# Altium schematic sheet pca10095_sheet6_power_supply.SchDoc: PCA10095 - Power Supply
size A3; Organization: Nordic Semiconductor; DocumentNumber: 6; SheetNumber: 6; SheetTotal: 6; CompanyName: Nordic Semiconductor
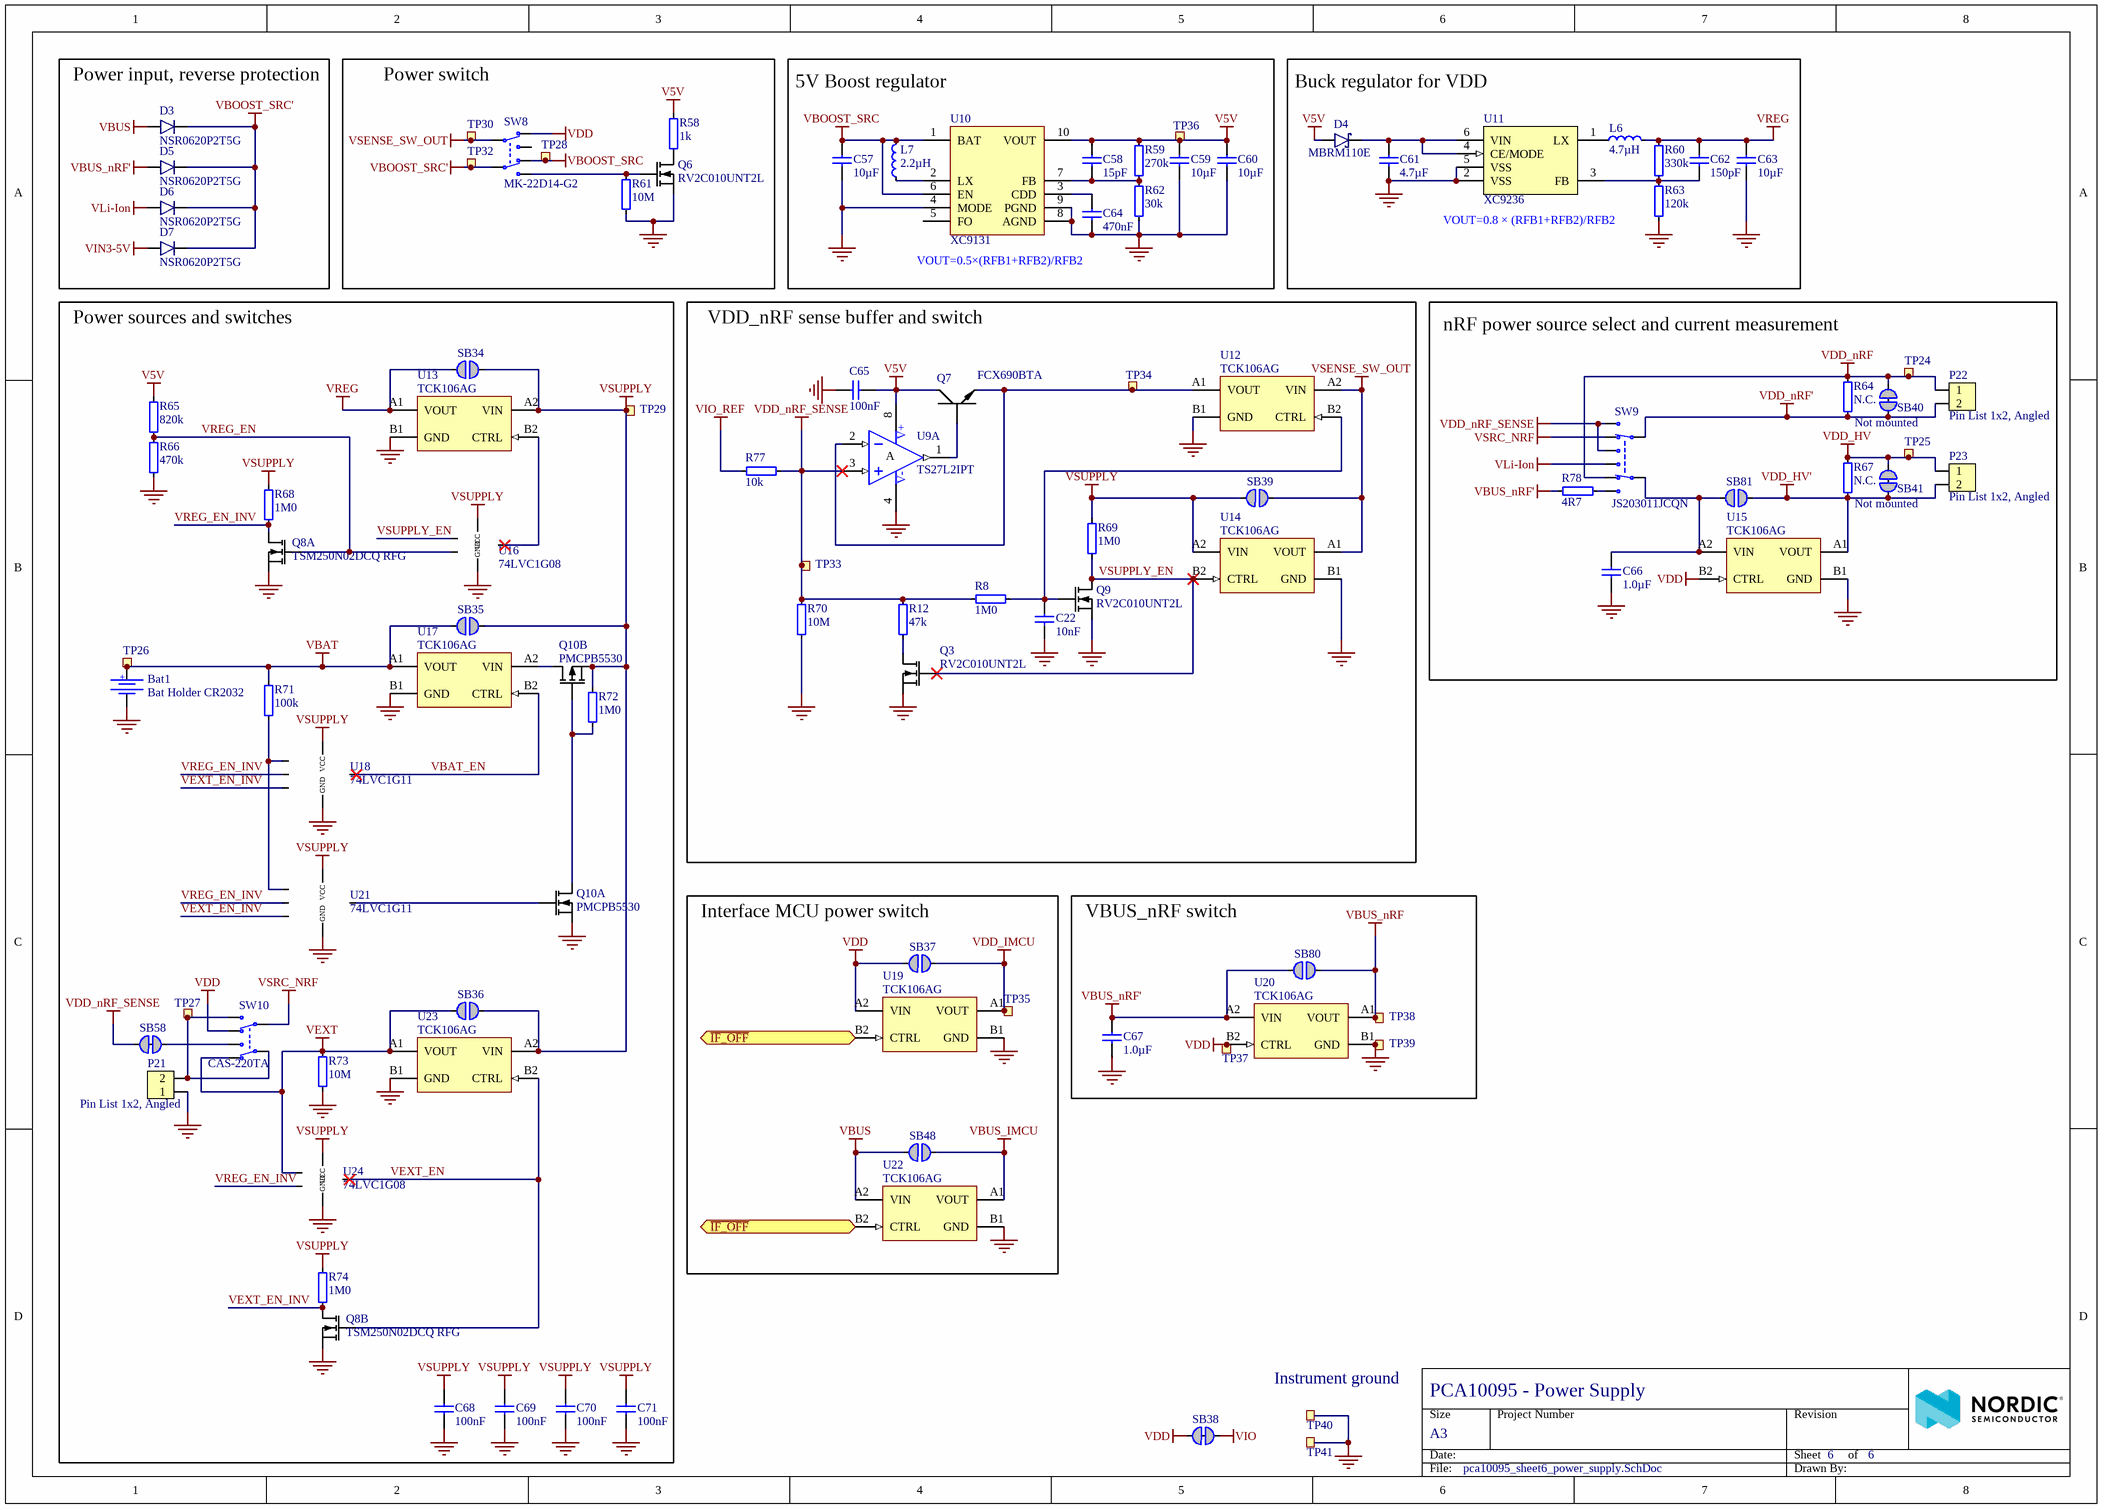
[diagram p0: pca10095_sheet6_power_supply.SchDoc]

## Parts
Bat1  Bat Holder CR2032  [L-KLS5-CR2032-23-B1]
C22  10nF  [CAPC0603X03L_C]
C57  10µF  [CAPC1608X06L]
C58  15pF  [CAPC0603X03L_C]
C59  10µF  [CAPC1608X06L]
C60  10µF  [CAPC1608X06L]
C61  4.7µF  [CAPC1005X04L]
C62  150pF  [CAPC0603X03L_C]
C63  10µF  [CAPC1608X06L]
C64  470nF  [CAPC0603X03L_C]
C65  100nF  [CAPC0603X03L_C]
C66  1.0µF  [CAPC1005X04L]
C67  1.0µF  [CAPC1608X06L]
C68  100nF  [CAPC0603X03L_C]
C69  100nF  [CAPC0603X03L_C]
C70  100nF  [CAPC0603X03L_C]
C71  100nF  [CAPC0603X03L_C]
D3  NSR0620P2T5G  [SODFL100X40-2N]
D4  MBRM110E  [DO-216AA]
D5  NSR0620P2T5G  [SODFL100X40-2N]
D6  NSR0620P2T5G  [SODFL100X40-2N]
D7  NSR0620P2T5G  [SODFL100X40-2N]
L6  4.7µH  [TY-NR3015]
L7  2.2µH  [TY-NR3015]
P21  Pin List 1x2, Angled  [LIST_ANG_1x2-SMD-2.54MM]
P22  Pin List 1x2, Angled  [LIST_ANG_1x2-SMD-2.54MM]
P23  Pin List 1x2, Angled  [LIST_ANG_1x2-SMD-2.54MM]
Q3  RV2C010UNT2L  [DFN65P100X40-3L]
Q6  RV2C010UNT2L  [DFN65P100X40-3L]
Q7  FCX690BTA  [SOT89-150P409X160-3N]
Q8  TSM250N02DCQ RFG  [DFN65P200X200X80_HS-6N]  (parts A,B of 2)
Q9  RV2C010UNT2L  [DFN65P100X40-3L]
Q10  PMCPB5530  [PMCPB5530X]  (parts A,B of 2)
R8  1M0  [RESC0603X03L_C]
R12  47k  [RESC0603X03L_C]
R58  1k  [RESC0603X03L_C]
R59  270k  [RESC0603X03L_C]
R60  330k  [RESC0603X03L_C]
R61  10M  [RESC0603X03L_C]
R62  30k  [RESC0603X03L_C]
R63  120k  [RESC0603X03L_C]
R64  N.C.  Assembly: Not mounted  [RESC1005X04L_NC]
R65  820k  [RESC0603X03L_C]
R66  470k  [RESC0603X03L_C]
R67  N.C.  Assembly: Not mounted  [RESC1005X04L_NC]
R68  1M0  [RESC0603X03L_C]
R69  1M0  [RESC0603X03L_C]
R70  10M  [RESC0603X03L_C]
R71  100k  [RESC0603X03L_C]
R72  1M0  [RESC0603X03L_C]
R73  10M  [RESC0603X03L_C]
R74  1M0  [RESC0603X03L_C]
R77  10k  [RESC0603X03L_C]
R78  4R7  [RESC0603X03L_C]
SB34  Solderbridge  [Solderbridge]  (value not drawn)  (no BOM)
SB35  Solderbridge  [Solderbridge]  (value not drawn)  (no BOM)
SB36  Solderbridge  [Solderbridge]  (value not drawn)  (no BOM)
SB37  Solderbridge  [Solderbridge]  (value not drawn)  (no BOM)
SB38  Solderbridge  [Solderbridge_Shorted]  (value not drawn)  (net tie, no BOM)
SB39  Solderbridge  [Solderbridge]  (value not drawn)  (no BOM)
SB40  Solderbridge  [Solderbridge_Shorted]  (value not drawn)  (net tie, no BOM)
SB41  Solderbridge  [Solderbridge_Shorted]  (value not drawn)  (net tie, no BOM)
SB48  Solderbridge  [Solderbridge]  (value not drawn)  (no BOM)
SB58  Solderbridge  [Solderbridge_Shorted]  (value not drawn)  (net tie, no BOM)
SB80  Solderbridge  [Solderbridge]  (value not drawn)  (no BOM)
SB81  Solderbridge  [Solderbridge]  (value not drawn)  (no BOM)
SW8  MK-22D14-G2  [MK-22D14-G2]
SW9  JS203011JCQN  [Switch-Slide-J-Lead-DP3T-13x3.5mm]
SW10  CAS-220TA  [CAS-220TA]
TP24  Ø1.5mm,SMD  [TP_SMD_Ø1.5mm]  (value not drawn)  (no BOM)
TP25  Ø1.5mm,SMD  [TP_SMD_Ø1.5mm]  (value not drawn)  (no BOM)
TP26  Ø1.5mm,SMD  [TP_SMD_Ø1.5mm]  (value not drawn)  (no BOM)
TP27  Ø1.5mm,SMD  [TP_SMD_Ø1.5mm]  (value not drawn)  (no BOM)
TP28  Ø1.5mm,SMD  [TP_SMD_Ø1.5mm]  (value not drawn)  (no BOM)
TP29  Ø1.0mm,SMD  [TP_SMD_Ø1.0mm]  (value not drawn)  (no BOM)
TP30  Ø1.5mm,SMD  [TP_SMD_Ø1.5mm]  (value not drawn)  (no BOM)
TP32  Ø1.5mm,SMD  [TP_SMD_Ø1.5mm]  (value not drawn)  (no BOM)
TP33  Ø1.0mm,SMD  [TP_SMD_Ø1.0mm]  (value not drawn)  (no BOM)
TP34  Ø1.0mm,SMD  [TP_SMD_Ø1.0mm]  (value not drawn)  (no BOM)
TP35  Ø1.5mm,SMD  [TP_SMD_Ø1.5mm]  (value not drawn)  (no BOM)
TP36  Ø1.0mm,SMD  [TP_SMD_Ø1.0mm]  (value not drawn)  (no BOM)
TP37  Ø1.5mm,SMD  [TP_SMD_Ø1.5mm]  (value not drawn)  (no BOM)
TP38  Ø1.5mm,SMD  [TP_SMD_Ø1.5mm]  (value not drawn)  (no BOM)
TP39  Ø1.5mm,SMD  [TP_SMD_Ø1.5mm]  (value not drawn)  (no BOM)
TP40  TP  [TESTPAD-TH]  (value not drawn)  (no BOM)
TP41  TP  [TESTPAD-TH]  (value not drawn)  (no BOM)
U9  TS27L2IPT  [TSOP65P640X120-8N]  (part A of 2)
U10  XC9131  [10-USPB (2.9x2.6)]
U11  XC9236  [USP-6C]
U12  TCK106AG  [BGA4C40P2X2_76X76X62]
U13  TCK106AG  [BGA4C40P2X2_76X76X62]
U14  TCK106AG  [BGA4C40P2X2_76X76X62]
U15  TCK106AG  [BGA4C40P2X2_76X76X62]
U16  74LVC1G08  [SOT65P210X100-5N]
U17  TCK106AG  [BGA4C40P2X2_76X76X62]
U18  74LVC1G11  [SOT65P210X100-6N]
U19  TCK106AG  [BGA4C40P2X2_76X76X62]
U20  TCK106AG  [BGA4C40P2X2_76X76X62]
U21  74LVC1G11  [SOT65P210X100-6N]
U22  TCK106AG  [BGA4C40P2X2_76X76X62]
U23  TCK106AG  [BGA4C40P2X2_76X76X62]
U24  74LVC1G08  [SOT65P210X100-5N]

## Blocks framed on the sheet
Power input, reverse protection: D3 D5-D7
Power switch: Q6 R58 R61 SW8 TP28 TP30 TP32
5V Boost regulator: C57-C60 C64 L7 R59 R62 TP36 U10
Buck regulator for VDD: C61-C63 D4 L6 R60 R63 U11
Power sources and switches: Bat1 C68-C71 P21 Q8 Q10 R65 R66 R68 R71-R74 SB34-SB36 SB58 SW10 TP26 TP27 TP29 U13 U16-U18 U21 U23 U24
VDD_nRF sense buffer and switch: C22 C65 Q3 Q7 Q9 R8 R12 R69 R70 R77 SB39 TP33 TP34 U9 U12 U14
nRF power source select and current measurement: C66 P22 P23 R64 R67 R78 SB40 SB41 SB81 SW9 TP24 TP25 U15
Interface MCU power switch: SB37 SB48 TP35 U19 U22
VBUS_nRF switch: C67 SB80 TP37-TP39 U20

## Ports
~{IF_OFF} (bidir)

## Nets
GND: Bat1.2 C22.2 C57.1 C59.1 C60.1 C61.1 C63.1 C64.1 C65.1 C66.1 C67.1 C68.1 C69.1 C70.1 C71.1 P21.1 Q3.2(S) Q6.2(S) Q8.1(S1) Q8.4(S2) Q9.2(S) Q10.1(S1) R61.2 R62.1 R63.1 R66.2 R70.2 R73.2 TP39.1 TP40.1 TP41.1 U9.4(V-) U10.4(MODE) U10.8(AGND) U10.9(PGND) U10.11(GND) U11.2(VSS) U11.5(VSS) U11.7(VSS) U12.B1(GND) U13.B1(GND) U14.B1(GND) U15.B1(GND) U16.3(GND) U17.B1(GND) U18.2(GND) U19.B1(GND) U20.B1(GND) U21.2(GND) U22.B1(GND) U23.B1(GND) U24.3(GND)
V5V: C58.2 C59.2 C60.2 C65.2 D4.1(A) Q7.2(C) R58.1 R59.2 R65.1 TP36.1 U9.8(V+) U10.10(VOUT)
VBAT: Bat1.1 R71.1 SB35.2 TP26.1 U17.A1(VOUT)
VBOOST_SRC: C57.2 L7.2 SW8.6(N.C-2) TP28.1 U10.1(BAT) U10.6(EN)
VBOOST_SRC': D3.1(C) D5.1(C) D6.1(C) D7.1(C) SW8.5(COM-2) TP32.1
VBUS: D3.2(A) SB48.2 U22.A2(VIN)
VBUS_IMCU: SB48.1 U22.A1(VOUT)
VBUS_nRF: SB80.1 TP38.1 U20.A1(VOUT)
VBUS_nRF': C67.2 D5.2(A) R78.1 SB80.2 U20.A2(VIN)
VDD: SB37.2 SB38.2 SW8.3(N.C-1) SW10.6(N.C-2) TP37.1 U15.B2(CTRL) U19.A2(VIN) U20.B2(CTRL)
VDD_HV: P23.1 R67.2 SB41.1 TP25.1
VDD_HV': P23.2 R67.1 SB41.2 SB81.1 U15.A1(VOUT)
VDD_IMCU: SB37.1 TP35.1 U19.A1(VOUT)
VDD_nRF: P22.1 R64.2 SB40.1 SW9.6(N.C) TP24.1
VDD_nRF': P22.2 R64.1 SB40.2 SW9.3(COM)
VDD_nRF_SENSE: R8.1 R12.1 R70.1 R77.1 SB58.1 SW9.1(N.O) SW9.4(N.O) TP33.1 U9.3(IN1+)
VEXT: R73.1 SB36.2 SW10.3(N.C-1) U23.A1(VOUT) U24.1(A)
VIN3-5V: D7.2(A)
VIO: SB38.1
VIO_REF: R77.2
VLi-Ion: D6.2(A) SW9.5(N.O)
VREG: C62.2 C63.2 L6.2 R60.2 SB34.2 U13.A1(VOUT)
VSENSE_SW_OUT: SB39.1 SW8.2(COM-1) TP30.1 U12.A2(VIN) U14.A1(VOUT)
VSRC_NRF: SW9.2(N.C) SW10.5(COM-2)
VSUPPLY: C68.2 C69.2 C70.2 C71.2 Q10.4(S2) R68.1 R69.1 R72.1 R74.1 SB34.1 SB35.1 SB36.1 SB39.2 TP29.1 U13.A2(VIN) U14.A2(VIN) U16.5(VCC) U18.5(VCC) U21.5(VCC) U23.A2(VIN) U24.5(VCC)
~{IF_OFF}: U19.B2(CTRL) U22.B2(CTRL) ; port ~{IF_OFF}
VBAT_EN: U17.B2(CTRL) U18.4(Y)
VEXT_EN: Q8.5(G2) U23.B2(CTRL) U24.4(Y)
VEXT_EN_INV: Q8.3(D2) R74.2 U18.6(C) U21.6(C)
VREG_EN: Q8.2(G1) R65.2 R66.1 U16.2(B)
VREG_EN_INV: Q8.6(D1) R68.2 U18.3(B) U21.3(B) U24.2(B)
VSUPPLY_EN: Q3.1(G) Q9.3(D) R69.2 U14.B2(CTRL) U16.1(A)
NetC22_1: C22.1 Q9.1(G) R8.2 U12.B2(CTRL)
NetC58_1: C58.1 R59.1 R62.2 U10.7(FB)
NetC61_2: C61.2 D4.3(C) U11.4(CE/MODE) U11.6(VIN)
NetC62_1: C62.1 R60.1 R63.2 U11.3(FB)
NetC64_2: C64.2 U10.3(CDD)
NetC66_2: C66.2 SB81.2 SW9.7(COM) U15.A2(VIN)
NetL6_1: L6.1 U11.1(LX)
NetL7_1: L7.1 U10.2(LX)
NetP21_2: P21.2 SW10.2(COM-1) SW10.4(N.O-2) TP27.1
NetQ3_3: Q3.3(D) R12.2
NetQ6_1: Q6.1(G) R61.1 SW8.4(N.O-2)
NetQ6_3: Q6.3(D) R58.2
NetQ7_1: Q7.1(B) U9.1(OUT1)
NetQ7_3: Q7.3(E) TP34.1 U9.2(IN1-) U12.A1(VOUT)
NetQ10_2: Q10.2(G1) U21.4(Y)
NetQ10_3: Q10.3(D2) U17.A2(VIN)
NetQ10_5: Q10.5(G2) Q10.6(D1) R72.2
NetR71_2: R71.2 U18.1(A) U21.1(A)
NetR78_2: R78.2 SW9.8(N.O)
NetSB58_2: SB58.2 SW10.1(N.O-1)
NetU13_B2: U13.B2(CTRL) U16.4(Y)

Not connected (* = marked no-connect by the designer): SW8 1(N.O-1); U10 5(FO)

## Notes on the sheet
- VOUT=0.8 × (RFB1+RFB2)/RFB2
- VOUT=0.5×(RFB1+RFB2)/RFB2
- (near TP40) Instrument ground

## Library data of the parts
Bat1 = Bat Holder L-KLS5-CR2032-23-B1: Bat Holder CR2032 SMD; Manufacturer: KLS Electronic; Artikkelnr Noca: N.A.; Pad Count: 2
C22 = C0201-10n: Capacitor, X7R, ±10%; Manufacturer: N.A.; Part number IPS: 00000003480; Note: 10V; Pad Count: 2
C57 C59 C60 C63 = C0603-10µ-25V: Capacitor, X5R, ±20%, 25V; Manufacturer: Samsung Electro-Mechanics America; Manufacturer Part Number: CL10A106MA8NRNC; Part number IPS: 00000009948; Part number Norautron: N.A.; Artikkelnr Noca: 20039436; Pad Count: 2
C58 = C0201-15p-25V-COG: Ceramic Capacitor C0G, NP0 0201, ±5% 25V; Manufacturer: Walsin Technology Corporation; Manufacturer Part Number: 0201N150J250CT; Note: Chip Cap 5%; Artikkelnr Noca: N.A.; Pad Count: 2
C61 = C0402-4µ7-10V-X5R: CAP CER 4.7UF 10V X5R 0402; Manufacturer: Murata; Manufacturer Part Number: GRM155R61A475MEAAD; Artikkelnr Noca: N.A.; Pad Count: 2
C62 = C0201-150p-25V-COG: Ceramic Capacitor C0G, NP0 0201, ±5% 25V; Manufacturer: Murata; Manufacturer Part Number: GRM0335C1E151JA01D; Note: Chip Cap 5%; Artikkelnr Noca: N.A.; Pad Count: 2
C64 = C0201-470n-16V-X5R: Ceramic Capacitor X5R 0201, ±10% 16V; Manufacturer: Taiyo Yuden; Manufacturer Part Number: EMK063BBJ474KPLF; Artikkelnr Noca: N.A.; Pad Count: 2
C65 C68-C71 = C0201-100n: Capacitor, X5R, ±10%; Manufacturer: N.A.; Part number IPS: 00000001248, 00000002505; Note: 16V; Pad Count: 2
C66 = C0402-1µ0: Capacitor, X5R, ±5%, 6.3V; Manufacturer: N.A.; Part number IPS: 00000007786, 00000003457; Artikkelnr Noca: 20039235; Pad Count: 2
C67 = C0603-1µ0: Capacitor, X7R, ±10%; Manufacturer: N.A.; Part number IPS: 00000000616; Note: 16V; Artikkelnr Noca: 20039282; Pad Count: 2
D3 D5-D7 = NSR0620P2T5G: 20V schottky barrier diode, Vf 350 mV @ 100 mA, Ir 2.0 µA @ 10 V, If 500 mA; Manufacturer: ON Semiconductor; Part number IPS: 00000009952; Note: N.A.; Artikkelnr Noca: 10029169; Pad Count: 2
D4 = MBRM110E: Diode Schottky Vf=0.455V @ 100mA, Vr=10V, If=1000mA, Ir=1µA @ 10V; Manufacturer: ON Semiconductor; Manufacturer Part Number: MBRM110ET1G; Part number IPS: 00000009953; Note: N.A.; Artikkelnr Noca: 10029172; Pad Count: 2
L6 = NR3015-4µ7-1.04A-144mOhm: Ferrite Inductor, Shielded, 1,04A, 144mOhm; Manufacturer: Taiyo Yuden; Manufacturer Part Number: NR3015T4R7M; Part number IPS: 00000009960; Note: N.A.; Artikkelnr Noca: 33029551; Pad Count: 2
L7 = NR3015-2µ2-1.5A-72mOhm: Ferrite Inductor, Shielded, 1,5A, 72mOhm; Manufacturer: Taiyo Yuden; Manufacturer Part Number: NR3015T2R2M; Part number IPS: 00000009959; Note: N.A.; Artikkelnr Noca: 33029487; Pad Count: 2
P21-P23 = Pin List Ang 1x2 SMD, 2.54mm: Pin List 1x2, 2.54mm (100mil), Right Angled, SMD; Manufacturer: W-CON; Manufacturer Part Number: 1125B-1102S0Z135R2; Part number IPS: 00000009972; Note: N.A.; Artikkelnr Noca: 55010023; Pad Count: 2
Q3 Q6 Q9 = RV2C010UNT2L: N-Channel MOSFET, 20V, 1A, 470mOhm, 400mW; Manufacturer: Rohm Semiconductor; Part number IPS: 00000009976; Note: N.A.; Artikkelnr Noca: 35010020; Pad Count: 3
Q7 = FCX690BTA: 45V NPN high gain power transistor; Manufacturer: Diodes Incorporated; Part number IPS: 00000009974; Note: N.A.; Artikkelnr Noca: 35010019; Pad Count: 3
Q8 = TSM250N02DCQ RFG: Dual N Ch MOFET, 5.8A, 55mOhm max, 620mW; Manufacturer: Taiwan Semiconductor; Part number IPS: 00000001703; Note: N.A.; Pad Count: 6
Q10 = PMCPB5530X,115: Mosfet Array N and P-Channel 20V 4A (Ta), 3.4A (Ta) 490mW Surface Mount 6-HUSON-EP (2x2); Manufacturer: Nexperia; Part number IPS: 00000001918; Note: N.A.; Pad Count: 8
R8 R68 R69 R72 R74 = R0201-1M0: Resistor, ±1%, 0.05W; Manufacturer: N.A.; Part number IPS: 00000001418; Note: Chip Res 1%; Pad Count: 2
R12 = R0201-47k: Resistor, ±1%, 0.05W; Manufacturer: N.A.; Part number IPS: 00000001423; Note: Chip Res 1%; Pad Count: 2
R58 = R0201-1k0: Resistor, ±1%, 0.05W; Manufacturer: N.A.; Part number IPS: 00000005786; Note: Chip Res 1%; Pad Count: 2
R59 = R0201-270k: Resistor, ±1%, 0.05W; Manufacturer: N.A.; Part number IPS: 00000004317; Note: Chip Res 1%; Pad Count: 2
R60 = R0201-330k: Resistor, ±1%, 0.05W; Manufacturer: N.A.; Part number IPS: 00000001424; Note: Chip Res 1%; Pad Count: 2
R61 R70 R73 = R0201-10M: Resistor, ±1%, 0.05W; Manufacturer: N.A.; Part number IPS: 00000001426; Note: Chip Res 1%; Pad Count: 2
R62 = R0201-30k: Resistor, ±1%, 0.05W; Manufacturer: N.A.; Part number IPS: 00000004318; Note: Chip Res 1%; Pad Count: 2
R63 = R0201-120k: Resistor, ±1%, 0.05W; Manufacturer: N.A.; Part number IPS: 00000001425; Note: Chip Res 1%; Pad Count: 2
R64 R67 = R0402-N.C.: Not mounted; Manufacturer: N.A.; Note: Chip Res; Pad Count: 2
R65 = R0201-820k: Resistor, ±1%, 0.05W; Manufacturer: N.A.; Part number IPS: 00000001427; Note: Chip Res 1%; Pad Count: 2
R66 = R0201-470k: Resistor, ±1%, 0.05W; Manufacturer: N.A.; Part number IPS: 00000001428; Note: Chip Res 1%; Pad Count: 2
R71 = R0201-100k: Resistor, ±1%, 0.05W; Manufacturer: N.A.; Part number IPS: 00000001419; Note: Chip Res 1%; Pad Count: 2
R77 = R0201-10k: Resistor, ±1%, 0.05W; Manufacturer: N.A.; Part number IPS: 00000001255; Note: Chip Res 1%; Pad Count: 2
R78 = R0201-4R7: Resistor, ±1%, 0.05W; Manufacturer: N.A.; Part number IPS: 00000002486; Note: Chip Res 1%; Pad Count: 2
SB34-SB37 SB39 SB48 SB80 SB81 = Solderbridge: Manufacturer: N.A.; Pad Count: 2
SB38 SB40 SB41 SB58 = Solderbridge Shorted: Shorted Solderbridge; Manufacturer: N.A.; Pad Count: 2
SW8 = MK-22D14-G2: Slide Switch DPDT; Manufacturer: HUA-JIE CORP.; Note: N.A.; Pad Count: 6
SW9 = JS203011JCQN: Slide Switch DP3T 300mA 6V; Manufacturer: C&K; Part number IPS: 00000004321; Note: N.A.; Artikkelnr Noca: 50019116; Pad Count: 8
SW10 = CAS-220TA: Slide Switch DPDT J Hook; Manufacturer: Copal Electronics Inc; Part number IPS: 00000009983; Note: N.A.; Artikkelnr Noca: 50019042; Pad Count: 6
TP24-TP28 TP30 TP32 TP35 TP37-TP39 = TP_SMD_Ø1.5MM: 1.5mm circular SMD testpad; Manufacturer: Nordic Semiconductor; Manufacturer Part Number: N.A.; Pad Count: 1
TP29 TP33 TP34 TP36 = TP_SMD_Ø1.0MM: 1.0mm circular SMD testpad; Manufacturer: Nordic Semiconductor; Manufacturer Part Number: N.A.; Pad Count: 1
TP40 TP41 = Testpoint TH: Testpoint, through hole; Manufacturer: N.A.; Pad Count: 1
U9 = TS27L2IPT: Precision very low power CMOS dual operational amplifier; Manufacturer: STMicroelectronics; Part number IPS: 00000009991; Note: N.A.; Artikkelnr Noca: 17010019; Pad Count: 8
U10 = XC9131H05CDR-G: 1A Driver Transistor Built-In, Multi Functional Step-Up DC/DC Converter; Manufacturer: Torex Semiconductor; Part number IPS: 00000009990; Note: N.A.; Artikkelnr Noca: 17030086; Pad Count: 10
U11 = XC9236D08CER-G: 600mA Driver Transistor Built-In, Synchronous Step-Down DC/DC Converters; Manufacturer: Torex Semiconductor; Part number IPS: 00000004325; Note: N.A.; Artikkelnr Noca: 17030085; Pad Count: 6
U12-U15 U17 U19 U20 U22 U23 = TCK106AG: 1.0 A Load Switch IC with Slew Rate Control Driver in Ultra Small Package; Manufacturer: Toshiba; Manufacturer Part Number: TCK106AG,LF; Part number IPS: 00000004390; Note: N.A.; Pad Count: 4
U16 U24 = 74LVC1G08GW: Single 2-Input AND Gate; Manufacturer: NXP Semiconductors; Part number IPS: 00000009992; Artikkelnr Noca: 15049058; Pad Count: 5
U18 U21 = 74LVC1G11GW: Single 3-input AND gate; Manufacturer: NXP Semiconductors; Part number IPS: 00000001430; Artikkelnr Noca: 15079348; Pad Count: 6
